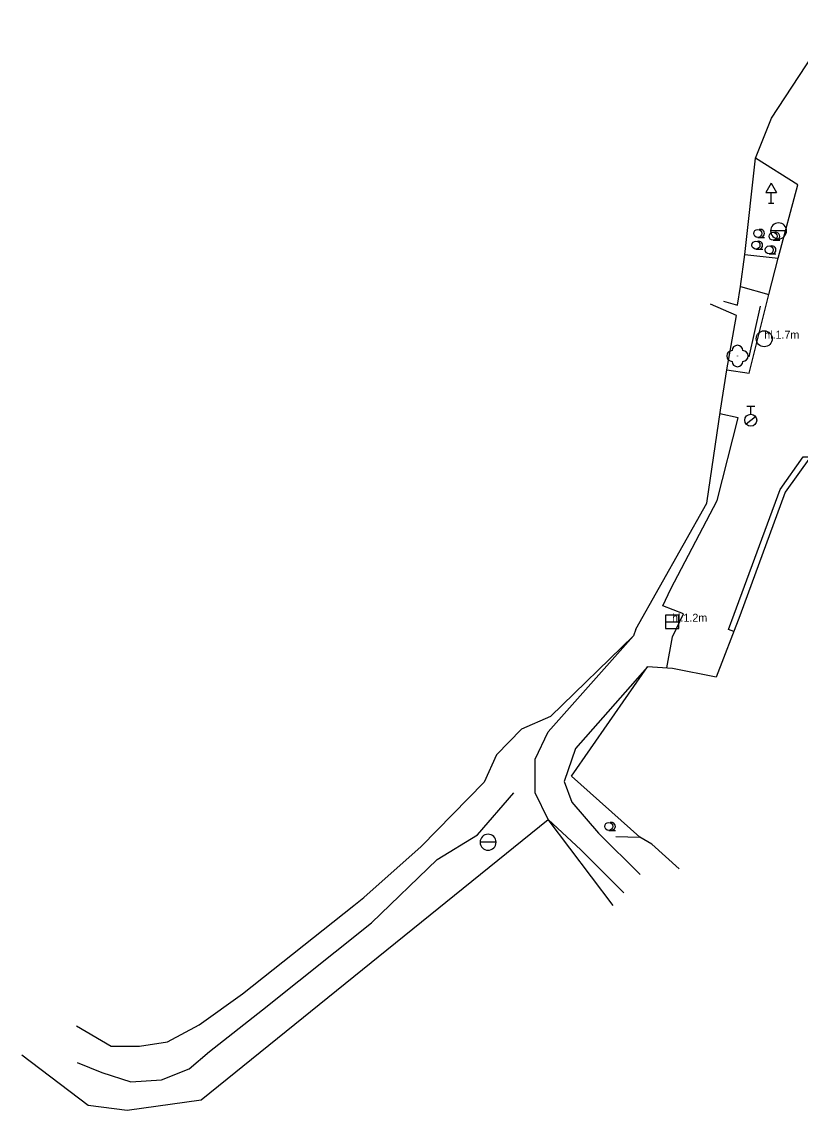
# Model space of a CAD drawing. Extents: x -747135 to -746147, y -1093269 to -1091735.
# Drawn here: x -746763 to -746690.1, y -1093185.1 to -1093083.1 of the extents above; entities that cross this region are included whole.
import ezdxf

# ---------------------------------------------------------------- set-up
doc = ezdxf.new("R2010")
doc.units = 0
for name, color, linetype in [('101', 7, 'Continuous'), ('1016', 7, 'Continuous'), ('1029', 7, 'Continuous'), ('105', 7, 'Continuous'), ('305', 7, 'Continuous'), ('306', 7, 'Continuous'), ('308', 7, 'Continuous'), ('316', 7, 'Continuous'), ('424', 7, 'Continuous'), ('803', 7, 'Continuous')]:
    doc.layers.add(name, color=color, linetype=linetype)

msp = doc.modelspace()

# ---------------------------------------------------------------- linework, layer by layer
at = {"layer": '101'}
msp.add_lwpolyline([(-746707.59, -1093165.95), (-746713.69, -1093157.88)], dxfattribs=at)
at = {"layer": '1016'}
for points in [[(-746696.94, -1093115.72), (-746694.86, -1093116.03), (-746693.01, -1093108.68), (-746692.13, -1093105.25), (-746690.31, -1093098.38), (-746694.28, -1093095.9)], [(-746695.26, -1093104.91), (-746692.13, -1093105.25)], [(-746695.68, -1093107.92), (-746693.01, -1093108.68)], [(-746702.56, -1093143.65), (-746702.03, -1093140.76), (-746701.01, -1093138.6), (-746702.96, -1093137.84), (-746702.2, -1093136.25), (-746697.85, -1093127.97), (-746695.89, -1093120.23), (-746697.61, -1093119.85)], [(-746696.29, -1093140.24), (-746696.81, -1093140.08), (-746696.26, -1093138.64), (-746691.96, -1093126.95), (-746689.81, -1093123.87), (-746689.12, -1093123.88)], [(-746706.59, -1093164.74), (-746710.65, -1093160.72), (-746713.69, -1093157.88), (-746714.93, -1093155.37), (-746714.91, -1093152.21), (-746713.7, -1093149.65), (-746705.7, -1093140.65)], [(-746704.4, -1093143.58), (-746711.15, -1093151.22), (-746712.2, -1093154.33), (-746711.47, -1093156.24), (-746708.98, -1093159.16), (-746705.08, -1093163.03)]]:
    msp.add_lwpolyline(points, dxfattribs=at)
at = {"layer": '1029'}
for p, q in [((-746694.05, -1093103.31), (-746693.43, -1093103.31)), ((-746694.22, -1093104.42), (-746693.59, -1093104.42)), ((-746692.62, -1093103.58), (-746691.99, -1093103.58)), ((-746692.98, -1093104.85), (-746692.35, -1093104.85)), ((-746708.02, -1093158.9), (-746707.4, -1093158.9))]:
    msp.add_line(p, q, dxfattribs=at)
for centre in [(-746694.05, -1093102.94), (-746692.62, -1093103.21), (-746694.22, -1093104.04), (-746692.98, -1093104.48), (-746708.02, -1093158.52)]:
    msp.add_circle(centre, 0.375, dxfattribs=at)
for centre in [(-746693.8, -1093102.94), (-746692.37, -1093103.21), (-746693.97, -1093104.04), (-746692.73, -1093104.48), (-746707.77, -1093158.52)]:
    msp.add_arc(centre, 0.375, 249.4944, 109.0474, dxfattribs=at)
at = {"layer": '305'}
for points in [[(-746694.28, -1093095.9), (-746692.77, -1093092.15)], [(-746697.55, -1093119.51), (-746696.94, -1093115.72)], [(-746697.94, -1093144.55), (-746702.05, -1093143.72)], [(-746718.54, -1093151.83), (-746716.21, -1093149.4)], [(-746703.97, -1093160.2), (-746705.09, -1093159.52)], [(-746731.9, -1093165.94), (-746730.97, -1093165.2)]]:
    msp.add_lwpolyline(points, dxfattribs=at)
at = {"layer": '306'}
for p, q in [((-746692.79, -1093098.24), (-746693.29, -1093099.11)), ((-746692.79, -1093098.24), (-746692.29, -1093099.11)), ((-746693.29, -1093099.11), (-746692.29, -1093099.11)), ((-746692.79, -1093100.11), (-746692.79, -1093099.11)), ((-746693.04, -1093100.11), (-746692.54, -1093100.11))]:
    msp.add_line(p, q, dxfattribs=at)
at = {"layer": '308'}
for points in [[(-746692.77, -1093092.15), (-746687.57, -1093084.22), (-746687.22, -1093083.69), (-746687.2, -1093083.32), (-746687.58, -1093083.1)], [(-746695.26, -1093104.91), (-746694.28, -1093095.9)], [(-746695.68, -1093107.92), (-746695.26, -1093104.91)], [(-746697.26, -1093109.28), (-746695.95, -1093109.67), (-746695.68, -1093107.92)], [(-746705.09, -1093159.52), (-746711.51, -1093153.83), (-746704.4, -1093143.58)], [(-746702.05, -1093143.72), (-746704.4, -1093143.58)]]:
    msp.add_lwpolyline(points, dxfattribs=at)
at = {"layer": '316'}
for p, q in [((-746691.35, -1093102.7), (-746692.85, -1093102.7)), ((-746695.08, -1093119.14), (-746694.33, -1093119.14)), ((-746694.71, -1093119.89), (-746694.71, -1093119.14)), ((-746695.15, -1093120.8), (-746694.27, -1093120.1)), ((-746701.45, -1093138.71), (-746702.71, -1093138.71)), ((-746702.71, -1093138.71), (-746702.71, -1093139.97)), ((-746701.45, -1093139.97), (-746701.45, -1093138.71)), ((-746702.71, -1093139.34), (-746701.46, -1093139.34)), ((-746702.71, -1093139.97), (-746701.45, -1093139.97)), ((-746718.58, -1093160.01), (-746720.08, -1093160.01))]:
    msp.add_line(p, q, dxfattribs=at)
for centre, radius in [((-746693.45, -1093112.81), 0.75), ((-746694.71, -1093120.45), 0.562)]:
    msp.add_circle(centre, radius, dxfattribs=at)
for centre, start, end in [((-746692.1, -1093102.7), 0, 180), ((-746692.1, -1093102.7), 180, 0), ((-746719.33, -1093160.01), 0, 180), ((-746719.33, -1093160.01), 180, 0)]:
    msp.add_arc(centre, 0.747, start, end, dxfattribs=at)
at = {"layer": '424'}
for points in [[(-746693.82, -1093109.75), (-746694.88, -1093114.52)], [(-746763.03, -1093179.93), (-746756.82, -1093184.65), (-746753.16, -1093185.13), (-746746.23, -1093184.14), (-746713.69, -1093157.88)]]:
    msp.add_lwpolyline(points, dxfattribs=at)
msp.add_circle((-746695.96, -1093114.43), 0.0005, dxfattribs=at)
for centre, start, end in [((-746695.96, -1093113.93), 0, 180), ((-746696.46, -1093114.43), 90, 270), ((-746695.46, -1093114.43), 270, 90), ((-746695.96, -1093114.93), 180, 360)]:
    msp.add_arc(centre, 0.5, start, end, dxfattribs=at)
at = {"layer": '803'}
for points in [[(-746696.94, -1093115.72), (-746696.05, -1093110.64), (-746698.49, -1093109.58)], [(-746705.49, -1093140.04), (-746698.84, -1093128.21), (-746697.55, -1093119.51)], [(-746687.62, -1093123.97), (-746688.59, -1093123.22), (-746689.12, -1093123.88), (-746691.49, -1093127.2), (-746695.73, -1093138.79), (-746697.94, -1093144.55)], [(-746705.49, -1093140.04), (-746705.7, -1093140.65), (-746713.48, -1093148.23), (-746716.21, -1093149.4)], [(-746718.54, -1093151.83), (-746719.68, -1093154.38)], [(-746730.97, -1093165.2), (-746725.61, -1093160.4), (-746719.68, -1093154.38)], [(-746757.84, -1093180.66), (-746755.53, -1093181.58), (-746752.8, -1093182.48), (-746749.92, -1093182.29), (-746747.35, -1093181.25), (-746745.44, -1093179.61), (-746740.47, -1093175.73), (-746730.24, -1093167.56), (-746724.11, -1093161.62), (-746720.33, -1093159.3), (-746716.92, -1093155.37)], [(-746707.37, -1093159.48), (-746705.09, -1093159.52)], [(-746701.41, -1093162.49), (-746703.97, -1093160.2)], [(-746757.91, -1093177.23), (-746754.66, -1093179.12), (-746752, -1093179.12), (-746749.36, -1093178.72), (-746746.39, -1093177.11), (-746742.33, -1093174.21), (-746731.9, -1093165.94)]]:
    msp.add_lwpolyline(points, dxfattribs=at)

# ---------------------------------------------------------------- texts
at = {"layer": '105'}
for s, p in [('hl.1.7m', (-746693.45, -1093112.81)), ('hl.1.2m', (-746702.08, -1093139.34))]:
    msp.add_text(s, height=0.75, dxfattribs=at).set_placement(p)

doc.saveas('drawing.dxf')
